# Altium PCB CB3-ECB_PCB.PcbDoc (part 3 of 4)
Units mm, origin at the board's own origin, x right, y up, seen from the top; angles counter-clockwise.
Board outline 195 x 139 mm, 4 copper layers (Top Layer, Layer 1, Layer 2, Bottom Layer), stack 1.56 mm thick; 363 components, 264 nets, 1430 pads, 630 vias.
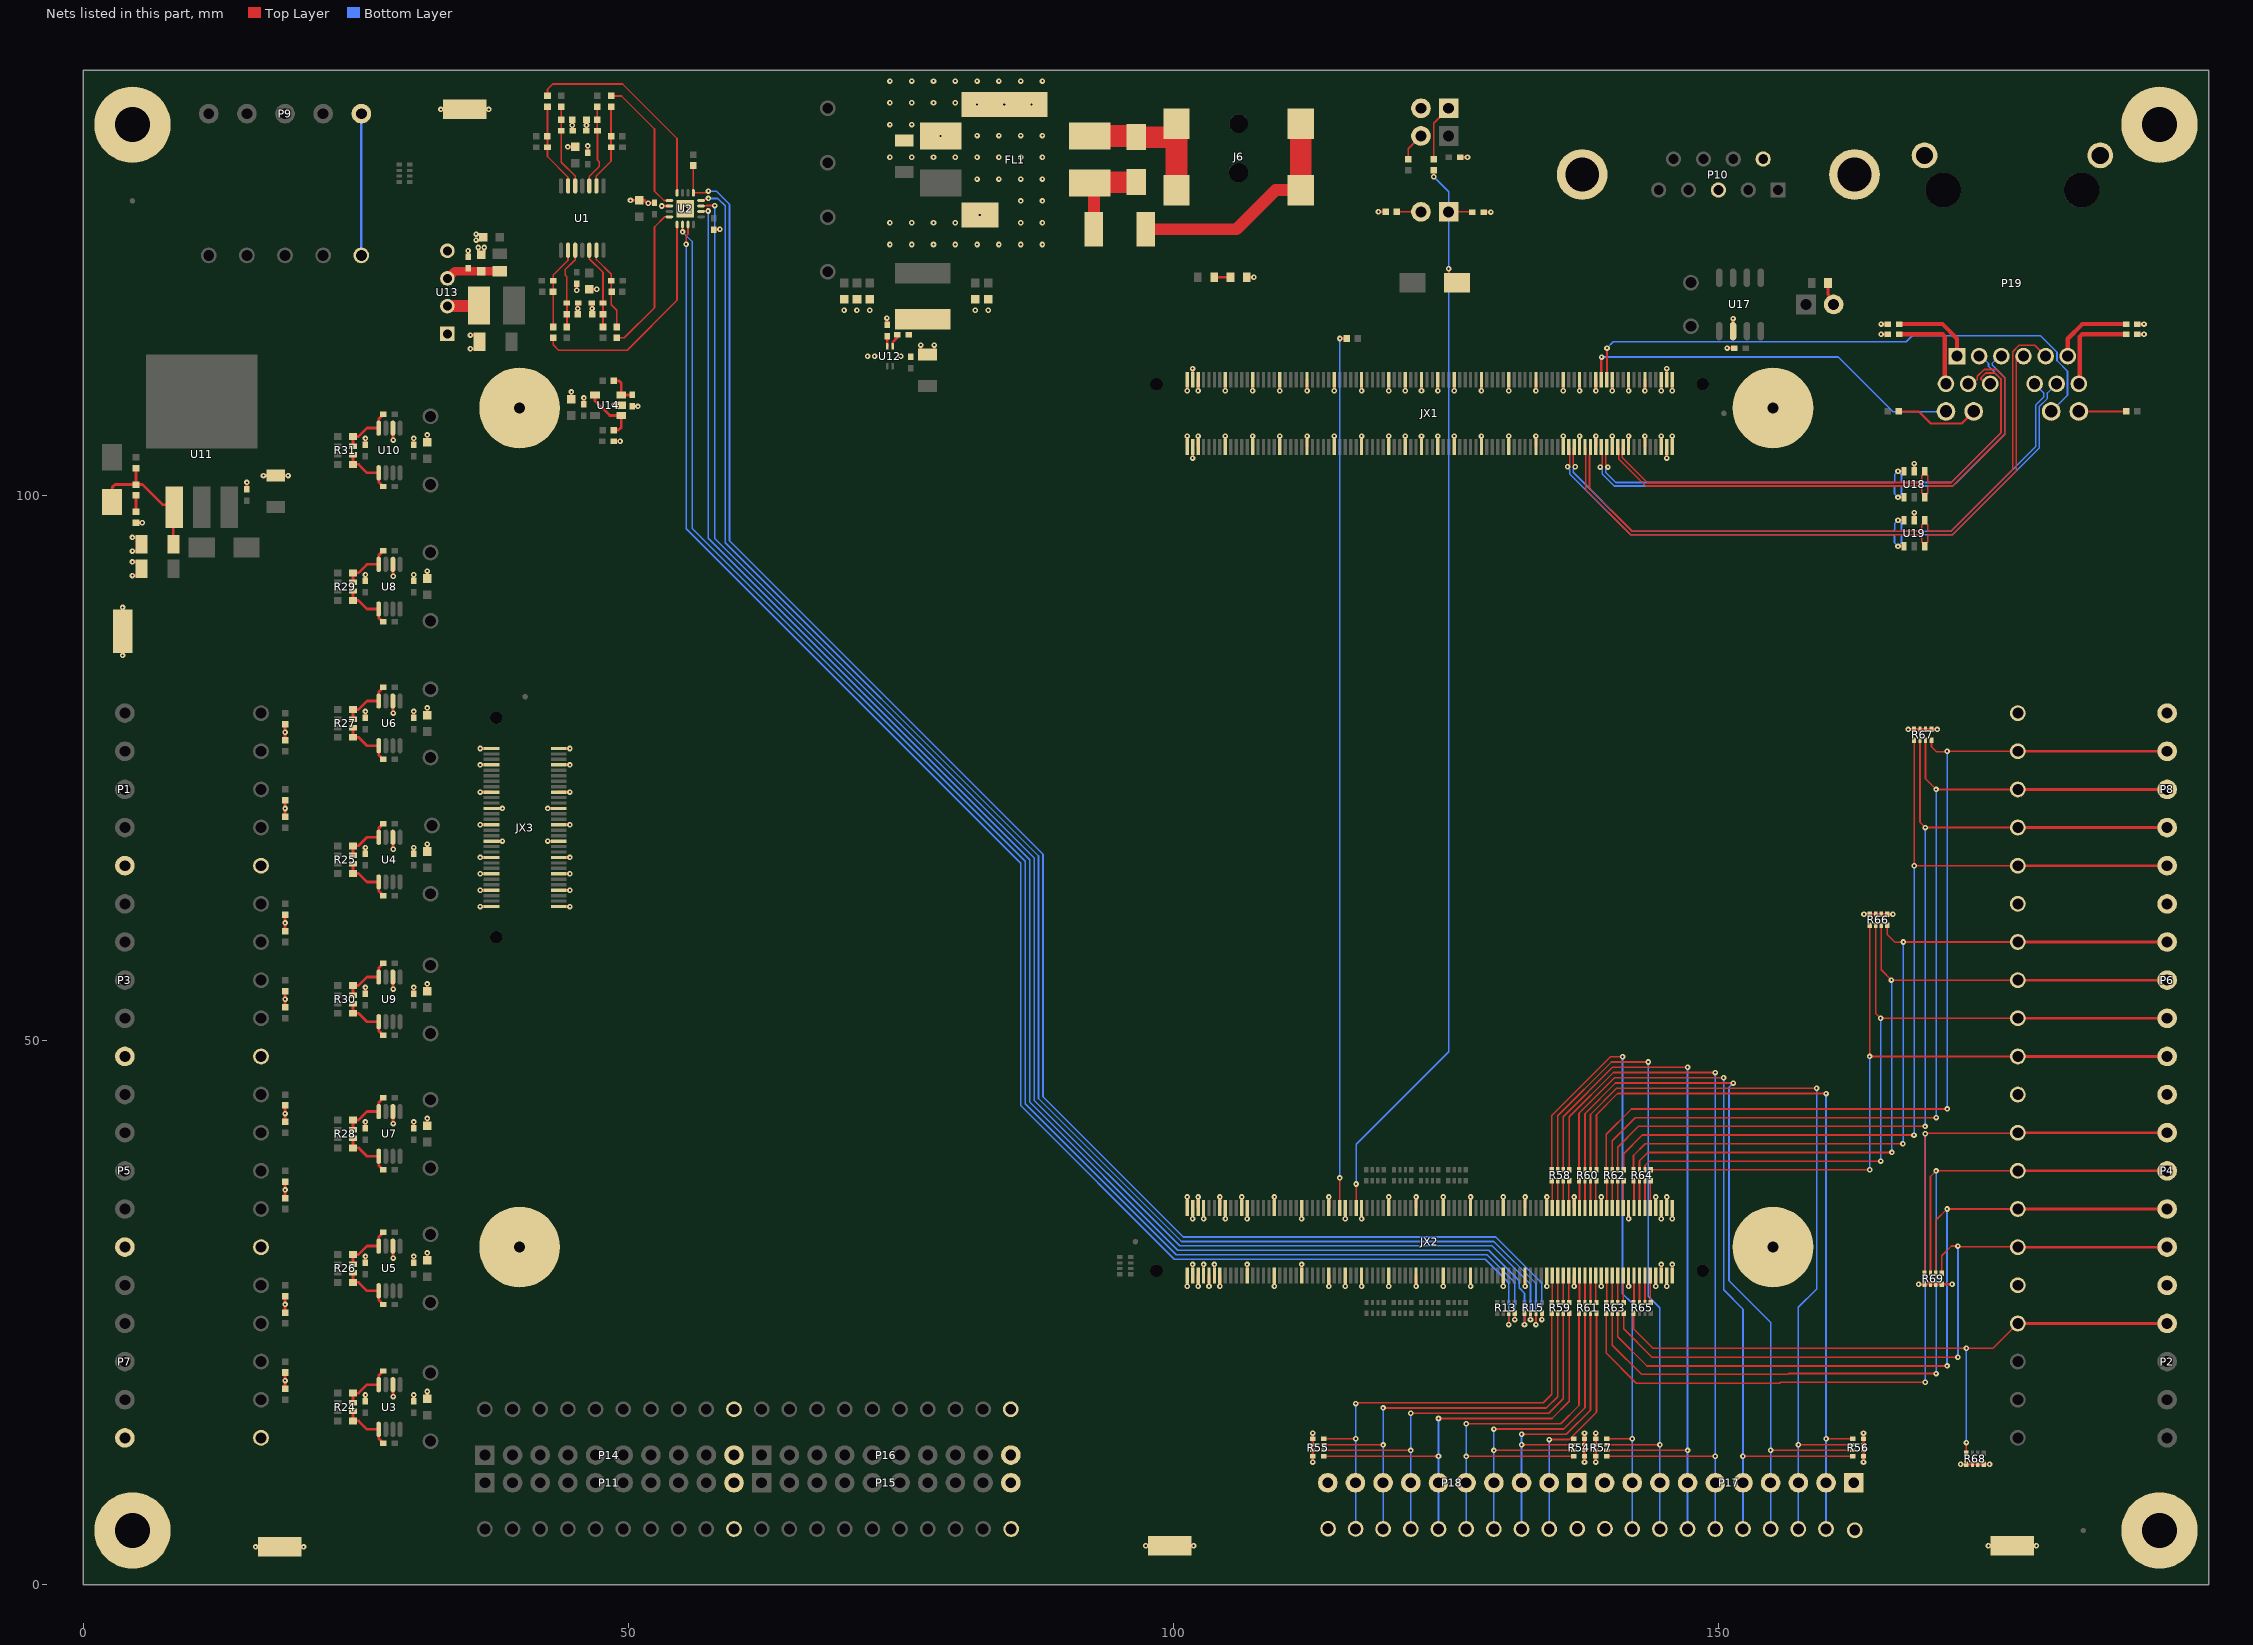
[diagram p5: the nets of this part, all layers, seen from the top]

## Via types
v1: diameter 0.508, hole 0.2, Top Layer to Bottom Layer, tented both sides, 435 vias
v2: diameter 0.508, hole 0.2, Top Layer to Bottom Layer, 194 vias
v3: diameter 0.66, hole 0.33, Top Layer to Bottom Layer, tented both sides, 1 vias

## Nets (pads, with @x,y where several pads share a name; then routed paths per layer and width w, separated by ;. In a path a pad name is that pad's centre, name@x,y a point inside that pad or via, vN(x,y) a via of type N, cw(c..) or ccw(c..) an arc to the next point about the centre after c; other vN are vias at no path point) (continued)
GND: C1.1 C2.1 C3.2 C4.2 C6.1 C7.1 C8.1 C9.1 C11.1 C13.1 C15.1 C18.1 C19.1 C20.1 C21.1 C22.1 C25.1 C28.1 C29.1 C30.1 C31.1 C32.1 C33.1 C38.1 C39.1 C40.1 C41.1 C42.1 C43.1 C46.1 C47.1 C50.1 C51.1 C52.1 C53.1 C56.1 C57.1 C59.1 C60.1 C61.1 C62.1 C63.1 C64.2 C65.2 C66.1 C67.2 C68.1 C69.1 C70.1 C71.1 C72.1 C73.1 C74.1 C75.1 C76.1 C77.1 C78.1 C79.1 C80.1 C81.1 C82.1 C83.1 C84.1 FL1.4 J1.1 J2.1 J3.1 J4.1 J5.1 JX1.1 JX1.2 JX1.3 JX1.6 JX1.9 JX1.12 JX1.15 JX1.18 JX1.21 JX1.26 JX1.31 JX1.36 JX1.41 JX1.44 JX1.47 JX1.50 JX1.53 JX1.58 JX1.63 JX1.68 JX1.73 JX1.78 JX1.83 JX1.88 JX1.89 JX1.90 JX1.91 JX1.92 JX1.93 JX1.98 JX1.103 JX1.108 JX1.113 JX1.118 JX1.123 JX1.128 JX1.131 JX1.134 JX1.137 JX1.140 JX1.145 JX1.150 JX1.155 JX1.160 JX1.163 JX1.166 JX1.169 JX1.172 JX1.175 JX1.178 JX1.179 JX1.180 JX2.1 JX2.2 JX2.3 JX2.4 JX2.7 JX2.8 JX2.11 JX2.12 JX2.17 JX2.22 JX2.27 JX2.30 JX2.33 JX2.38 JX2.43 JX2.48 JX2.53 JX2.59 JX2.63 JX2.67 JX2.72 JX2.77 JX2.82 JX2.87 JX2.88 JX2.89 JX2.90 JX2.91 JX2.92 JX2.93 JX2.94 JX2.99 JX2.104 JX2.109 JX2.114 JX2.118 JX2.122 JX2.128 JX2.133 JX2.138 JX2.143 JX2.148 JX2.151 JX2.154 JX2.159 JX2.164 JX2.169 JX2.174 JX2.175 JX2.176 JX2.177 JX2.178 JX2.179 JX2.180 JX3.1 JX3.4 JX3.9 JX3.12 JX3.15 JX3.18 JX3.21 JX3.24 JX3.27 JX3.30 JX3.31 JX3.34 JX3.37 JX3.40 JX3.43 JX3.46 JX3.49 JX3.52 JX3.57 JX3.60 LED1.K P1.1 P2.1 P3.1 P4.1 P5.1 P6.1 P7.1 P8.1 P9.5 P10.3 P10.6 P10.MH1 P10.MH2 P11.10 P13.2 P14.10 P15.10 P16.10 P17.1 P17.10 P18.1 P18.10 P19.S1 P19.S2 P22.0 P23.0 P24.0 P25.0 P26.1 P27.1 P28.1 P29.1 R3.1 R4.1 R8.1 R14.1 R19.1 R23.1 R34.1 R35.1 R37.1 R38.1 R39.1 R40.1 R54.5 R54.6 R54.7 R54.8 R55.5 R55.6 R55.7 R55.8 R56.5 R56.6 R56.7 R56.8 R57.5 R57.6 R57.7 R57.8 R66.5 R66.6 R66.7 R66.8 R67.5 R67.6 R67.7 R67.8 R68.5 R68.6 R68.7 R68.8 R69.5 R69.6 R69.7 R69.8 R71.1 R72.1 R73.1 R74.1 R75.1 R76.1 R77.1 R78.1 R79.1 R84.1 TP21.1 TP22.1 TP31.1 TP32.1 TP57.1 TP58.1 TP59.1 TP60.1 TP65.1 TP66.1 TP67.1 TP68.1 TP73.1 TP74.1 TP75.1 TP76.1 TP105.1 U2.2 U2.17 U3.6 U4.6 U5.6 U6.6 U7.6 U8.6 U9.6 U10.6 U12.1 U12.9 U13.1 U13.4 U14.2 U17.2 U18.2 U19.2 | length 251.3
  Top Layer w0.25: v2(4.5,92.625) C63.1@4.925,92.625 ; v2(4.5,93.875) C63.1@4.925,93.875 ; v2(4.5,94.875) C62.1@4.925,94.875 ; v2(4.5,96.125) 4.925,96.125 5.35,95.7 C62.1@5.35,95.5 ; R34.1@4.825,97.475 v2(5.4,97.475) ; C61.1@15,100.525 v2(15,101.175) ; v2(16.525,101.8) C60.1@17.65,101.8 v2(18.775,101.8) ; R76.1@18.5,18 v1(18.5,18.75) R77.1@18.5,19.5 ; R72.1@18.5,25 v1(18.5,25.75) R73.1@18.5,26.5 ; R38.1@18.5,35.5 v1(18.5,36.25) R39.1@18.5,37 ; R3.1@18.5,42.5 v1(18.5,43.25) R4.1@18.5,44 ; R78.1@18.5,53 v1(18.5,53.75) R79.1@18.5,54.5 ; R74.1@18.5,60 v1(18.5,60.75) R75.1@18.5,61.5 ; R40.1@18.5,70.5 v1(18.5,71.25) R71.1@18.5,72 ; R35.1@18.5,77.5 v1(18.5,78.25) R37.1@18.5,79 ; C67.2@35.3,121.875 v2(35.3,122.425) ; v2(35.508,113.437) C66.1@35.933,113.437 ; v2(35.508,114.687) C66.1@35.933,114.687 ; v2(36.025,123.4) C65.2@36.475,123.4 ; v2(36.025,123.95) C65.2@36.475,123.95 ; C64.2@36.225,122.275 v2(36.225,122.725) ; C64.2@36.275,122.275 C64.2@36.5,122.05 ; C64.2@36.775,122.275 v2(36.775,122.725) ; C79.1@44.775,108.8 v2(44.775,109.475) ; v1(45.272,118.8) C2.1@45.272,119.417 ; C77.1@45.925,108.35 v2(45.925,108.925) ; C4.2@46.27,131.435 v1(46.271,132.052) ; v2(48.65,108.25) U14.2@49.35,108.25 ; C81.1@48.675,104.95 v2(49.25,104.95) ; v1(50.2,127.05) C9.1@51,127.05 51.497,127.05 51.759,126.789 v1(51.828,126.789) ; C80.1@50.375,108.15 v2(50.875,108.15) ; v1@51.898,126.789 v1(51.828,126.789) ; C8.1@52.4,126.825 52.382,126.807 51.847,126.807 v1(51.828,126.789) ; v1(53.072,126.534) U2.2@53.772,126.534 ; C7.1@57.828,124.346 57.855,124.373 58.373,124.373 v1(58.4,124.4) ; v2(73.725,116.25) 73.738,116.237 73.738,115.663 C72.1@73.75,115.65 ; C68.1@76.825,113.35 v2(76.825,113.775) ; C68.1@78.075,113.35 v2(78.075,113.775) ; LED1.K@106.75,120 v2(107.4,120) ; v2(118.825,126) R84.1@119.5,126 ; C78.1@126.325,131 v2(127,131) ; C84.1@128.475,125.975 v2(129.15,125.975) ; v2(150.825,113.5) C70.1@151.475,113.5 ; U17.2@151.365,115.05 151.365,116.165 v2@151.4,116.2 ; v2(164.95,114.763) C76.1@165.55,114.763 ; v2(164.95,115.7) C75.1@165.55,115.7 ; U19.2@168,97.7 v1(168,98.4) ; U18.2@168,102.2 v1(168,102.9) ; C73.1@188.475,114.763 v2(189.075,114.763) ; C74.1@188.475,115.7 v2(189.075,115.7)
  Top Layer w0.254: C20.1@25.875,16.856 v1(25.875,17.432) ; C30.1@25.875,29.569 v1(25.875,30.145) ; C40.1@25.875,41.914 v1(25.875,42.489) ; C50.1@25.875,54.258 v1(25.875,54.834) ; C25.1@25.875,67.085 v1(25.875,67.661) ; C33.1@25.875,79.582 v1(25.875,80.158) ; C43.1@25.875,92.129 v1(25.875,92.705) ; C53.1@25.875,104.626 v1(25.875,105.202) ; U10.6@28.397,106.151 28.41,106.138 28.41,105.07 v1(28.429,105.051) ; v1@28.41,17.3 U3.6@28.41,18.368 ; v1@28.41,30.013 U5.6@28.41,31.081 ; v1@28.41,42.358 U7.6@28.41,43.426 ; v1@28.41,54.702 U9.6@28.41,55.77 ; v1@28.41,67.529 U4.6@28.41,68.597 ; v1@28.41,80.026 U6.6@28.41,81.094 ; v1@28.41,92.573 U8.6@28.41,93.641 ; C18.1@30.305,16.856 v1(30.305,17.433) ; C21.1@30.305,29.569 v1(30.305,30.145) ; C28.1@30.305,41.914 v1(30.305,42.49) ; C31.1@30.305,54.258 v1(30.305,54.834) ; C38.1@30.305,67.085 v1(30.305,67.661) ; C41.1@30.305,79.582 v1(30.305,80.158) ; C46.1@30.305,92.129 v1(30.305,92.705) ; C51.1@30.305,104.626 v1(30.305,105.202) ; C52.1@31.548,104.851 31.55,104.853 v1(31.55,105.525) ; C19.1@31.548,17.081 v1(31.55,17.755) ; C22.1@31.55,29.796 v1(31.55,30.468) ; C29.1@31.55,42.141 v1(31.55,42.812) ; C32.1@31.55,54.485 v1(31.55,55.157) ; C39.1@31.55,67.312 v1(31.55,67.984) ; C42.1@31.55,79.809 v1(31.55,80.481) ; C47.1@31.55,92.356 v1(31.55,93.028) ; v1(36.421,62.255) JX3.31@37.435,62.255 ; v1(36.421,63.755) JX3.34@37.435,63.755 ; v1(36.421,65.255) JX3.37@37.435,65.255 ; v1(36.421,66.755) JX3.40@37.435,66.755 ; v1(36.421,69.755) JX3.46@37.435,69.755 ; v1(36.421,72.755) JX3.52@37.435,72.755 ; v1(36.421,75.255) JX3.57@37.435,75.255 ; v1(36.421,76.755) JX3.60@37.435,76.755 ; JX3.43@37.435,68.255 v1(38.45,68.255) ; JX3.49@37.435,71.255 v1(38.45,71.255) ; v1(42.611,68.255) JX3.18@43.625,68.255 ; v1(42.611,71.255) JX3.12@43.625,71.255 ; JX3.30@43.625,62.255 v1(44.64,62.255) ; JX3.27@43.625,63.755 v1(44.64,63.755) ; JX3.24@43.625,65.255 v1(44.64,65.255) ; JX3.21@43.625,66.755 v1(44.64,66.755) ; JX3.15@43.625,69.755 v1(44.64,69.755) ; JX3.9@43.625,72.755 v1(44.64,72.755) ; JX3.4@43.625,75.255 v1(44.64,75.255) ; JX3.1@43.625,76.755 v1(44.64,76.755) ; v1(44.443,131.952) C3.2@45.015,131.952 ; C15.1@44.852,133.432 v1(44.852,133.94) R23.1@44.852,134.448 ; R8.1@45.366,116.617 v1(45.366,117.125) C6.1@45.366,117.633 ; C13.1@46.162,133.432 v1(46.162,133.94) R19.1@46.162,134.448 ; C1.1@46.517,118.889 46.528,118.9 v1(47.1,118.9) ; R14.1@46.676,116.617 v1(46.676,117.125) C11.1@46.676,117.633 ; v1(101.28,27.409) JX2.180@101.28,28.41 ; JX2.1@101.28,34.6 v1(101.28,35.601) ; JX1.90@101.28,104.41 v1(101.28,105.422) ; v1(101.28,109.588) JX1.91@101.28,110.6 ; JX2.179@101.78,28.41 v1(101.78,29.411) ; v1(101.78,33.599) JX2.2@101.78,34.6 ; v1(101.78,103.398) JX1.89@101.78,104.41 ; JX1.92@101.78,110.6 v1(101.78,111.612) ; v1(102.28,27.409) JX2.178@102.28,28.41 ; JX2.3@102.28,34.6 v1(102.28,35.601) ; JX1.88@102.28,104.41 v1(102.28,105.422) ; v1(102.28,109.588) JX1.93@102.28,110.6 ; JX2.177@102.78,28.41 v1(102.78,29.411) ; v1(102.78,33.599) JX2.4@102.78,34.6 ; v1@103.28,27.409 JX2.176@103.28,28.41 ; JX2.175@103.78,28.41 v1(103.78,29.411) ; v1(104.28,27.409) JX2.174@104.28,28.41 ; JX2.7@104.28,34.6 v1(104.28,35.601) ; v1(104.78,33.599) JX2.8@104.78,34.6 ; JX1.83@104.78,104.41 v1(104.78,105.422) ; v1(104.78,109.588) JX1.98@104.78,110.6 ; JX2.11@106.28,34.6 v1(106.28,35.601) ; JX2.169@106.78,28.41 v1(106.78,29.411) ; v1(106.78,33.599) JX2.12@106.78,34.6 ; JX1.78@107.28,104.41 v1@107.28,105.422 ; v1@107.28,109.588 JX1.103@107.28,110.6 ; v1(109.28,27.409) JX2.164@109.28,28.41 ; JX2.17@109.28,34.6 v1(109.28,35.601) ; JX1.73@109.78,104.41 v1(109.78,105.422) ; v1(109.78,109.588) JX1.108@109.78,110.6 ; JX2.159@111.78,28.41 v1(111.78,29.411) ; v1(111.78,33.599) JX2.22@111.78,34.6 ; JX1.68@112.28,104.41 v1(112.28,105.422) ; v1(112.28,109.588) JX1.113@112.28,110.6 ; v1(112.796,11.28) R55.8@112.796,11.81 R55.7@112.796,12.36 R55.6@112.796,12.86 R55.5@112.796,13.41 v1(112.796,13.941) ; v1(114.28,27.409) JX2.154@114.28,28.41 ; JX2.27@114.28,34.6 v1(114.28,35.601) ; JX1.63@114.78,104.41 v1(114.78,105.422) ; v1(114.78,109.588) JX1.118@114.78,110.6 ; v1(115.78,27.409) JX2.151@115.78,28.41 ; v1(115.78,33.599) JX2.30@115.78,34.6 ; v1(117.28,27.409) JX2.148@117.28,28.41 ; v1(117.28,33.599) JX2.33@117.28,34.6 ; JX1.58@117.28,104.41 v1(117.28,105.422) ; v1(117.28,109.588) JX1.123@117.28,110.6 ; v1(119.78,27.409) JX2.143@119.78,28.41 ; JX2.38@119.78,34.6 v1(119.78,35.601) ; JX1.53@119.78,104.41 v1(119.78,105.422) ; v1(119.78,109.588) JX1.128@119.78,110.6 ; JX1.50@121.28,104.41 v1(121.28,105.422) ; v1(121.28,109.588) JX1.131@121.28,110.6 ; v1(122.28,27.409) JX2.138@122.28,28.41 ; JX2.43@122.28,34.6 v1(122.28,35.601) ; JX1.47@122.78,104.41 v1(122.78,105.422) ; v1(122.78,109.588) JX1.134@122.78,110.6 ; JX1.44@124.28,104.41 v1@124.28,105.422 ; v1@124.28,109.588 JX1.137@124.28,110.6 ; v1(124.78,27.409) JX2.133@124.78,28.41 ; JX2.48@124.78,34.6 v1(124.78,35.601) ; JX1.41@125.78,104.41 v1(125.78,105.422) ; v1(125.78,109.588) JX1.140@125.78,110.6 ; v1(127.28,27.409) JX2.128@127.28,28.41 ; JX2.53@127.28,34.6 v1(127.28,35.601) ; JX1.36@128.28,104.41 v1(128.28,105.422) ; v1(128.28,109.588) JX1.145@128.28,110.6 ; v1(130.28,27.409) JX2.122@130.28,28.41 ; JX2.59@130.28,34.6 v1(130.28,35.601) ; JX1.31@130.78,104.41 v1@130.78,105.422 ; v1@130.78,109.588 JX1.150@130.78,110.6 ; v1(132.28,27.409) JX2.118@132.28,28.41 ; JX2.63@132.28,34.6 v1(132.28,35.601) ; JX1.26@133.28,104.41 v1(133.28,105.422) ; v1(133.28,109.588) JX1.155@133.28,110.6 ; v1(134.28,27.409) JX2.114@134.28,28.41 ; JX2.67@134.28,34.6 v1(134.28,35.601) ; JX1.21@135.78,104.41 v1(135.78,105.422) ; v1(135.78,109.588) JX1.160@135.78,110.6 ; v1(136.78,27.409) JX2.109@136.78,28.41 ; JX2.72@136.78,34.6 v1(136.78,35.601) ; JX1.18@137.28,104.41 v1(137.28,105.422) ; v1(137.28,109.588) JX1.163@137.28,110.6 ; v1(137.736,11.28) R54.5@137.736,11.81 R54.6@137.736,12.36 R54.7@137.736,12.86 R54.8@137.736,13.41 v1(137.736,13.941) ; v1(138.768,11.28) R57.8@138.768,11.81 R57.7@138.768,12.36 R57.6@138.768,12.86 R57.5@138.768,13.41 v1(138.768,13.941) ; JX1.15@138.78,104.41 v1(138.78,105.422) ; v1(138.78,109.588) JX1.166@138.78,110.6 ; v1(139.28,27.409) JX2.104@139.28,28.41 ; JX2.77@139.28,34.6 v1(139.28,35.601) ; JX1.12@140.28,104.41 v1(140.28,105.422) ; v1(140.28,109.588) JX1.169@140.28,110.6 ; v1(141.78,27.409) JX2.99@141.78,28.41 ; v1(141.78,33.599) JX2.82@141.78,34.6 ; JX1.9@141.78,104.41 v1(141.78,105.422) ; v1(141.78,109.588) JX1.172@141.78,110.6 ; JX1.6@143.28,104.41 v1(143.28,105.422) ; v1(143.28,109.588) JX1.175@143.28,110.6 ; v1(144.28,27.409) JX2.94@144.28,28.41 ; JX2.87@144.28,34.6 v1(144.28,35.601) ; JX2.93@144.78,28.41 v1(144.78,29.411) ; v1(144.78,33.599) JX2.88@144.78,34.6 ; JX1.3@144.78,104.41 v1(144.78,105.422) ; v1(144.78,109.588) JX1.178@144.78,110.6 ; v1(145.28,27.409) JX2.92@145.28,28.41 ; JX2.89@145.28,34.6 v1(145.28,35.601) ; v1(145.28,103.398) JX1.2@145.28,104.41 ; JX1.179@145.28,110.6 v1(145.28,111.612) ; JX2.91@145.78,28.41 v1(145.78,29.411) ; v1(145.78,33.599) JX2.90@145.78,34.6 ; JX1.1@145.78,104.41 v1(145.78,105.422) ; v1(145.78,109.588) JX1.180@145.78,110.6 ; v1(163.336,11.28) R56.5@163.336,11.81 R56.6@163.336,12.36 R56.7@163.336,12.86 R56.8@163.336,13.41 v1(163.336,13.941) ; v1(163.38,61.549) R66.8@163.911,61.549 R66.7@164.461,61.549 R66.6@164.961,61.549 R66.5@165.511,61.549 v1(166.041,61.549) ; v1(167.444,78.504) R67.8@167.975,78.504 R67.7@168.525,78.504 R67.6@169.025,78.504 R67.5@169.575,78.504 v1(170.105,78.504) ; v1(168.397,27.601) R69.5@168.927,27.601 R69.6@169.477,27.601 R69.7@169.977,27.601 R69.8@170.527,27.601 v1(171.464,27.601) ; v1(172.248,11.073) R68.5@172.778,11.073 R68.6@173.328,11.073 R68.7@173.828,11.073 R68.8@174.378,11.073 v1(174.909,11.073)
  Top Layer w0.305: v1(3.6,85.3) J2.1@3.6,87.5 v1(3.6,89.7) ; v1(15.8,3.5) J4.1@18,3.5 v1(20.2,3.5) ; v1(32.8,135.4) J5.1@35,135.4 v1(37.2,135.4) ; v1(97.47,3.6) v1(101.87,3.6) ; v1(174.8,3.6) J1.1@177,3.6 v1(179.2,3.6)
  Bottom Layer w0.25: TP105.1@25.5,122 P9.5@25.5,135
  other v1: 28.429,17.281 103.28,27.409 28.429,29.994 28.429,42.339 28.429,54.683 28.429,67.51 28.429,80.007 28.429,92.554 107.28,105.422 124.28,105.422 130.78,105.422 107.28,109.588 124.28,109.588 130.78,109.588
  other v2: 71.95,112.75 72.6,112.75 75,112.75 151.365,116.2 69.8,116.975 70.975,116.975 72.15,116.975 81.825,116.975 83.025,116.975 74,123 76,123 78,123 80,123 82,123 84,123 86,123 88,123 74,125 76,125 78,125 80,125 86,125 88,125 82.25,125.7 86,127 88,127 82,129 84,129 86,129 88,129 74,131 76,131 78,131 80,131 82,131 84,131 86,131 88,131 78.65,132.95 82,133 84,133 86,133 88,133 74,134 76,134 82,135.85 84.5,135.85 87,135.85 74,136 76,136 78,136 80,136 74,138 76,138 78,138 80,138 82,138 84,138 86,138 88,138
  other v3: 55.222,126.284
GPI0: JX2.105 R61.5 | length 2.5
  Top Layer w0.152: R61.5@138.78,25.92 JX2.105@138.78,28.41
GPI1: JX2.106 R61.6 | length 2.5
  Top Layer w0.152: R61.6@138.28,25.92 JX2.106@138.28,28.41
GPI2: JX2.107 R61.7 | length 2.5
  Top Layer w0.152: R61.7@137.78,25.92 JX2.107@137.78,28.41
GPI3: JX2.108 R61.8 | length 2.5
  Top Layer w0.152: R61.8@137.28,25.92 JX2.108@137.28,28.41
GPI4: JX2.110 R59.5 | length 2.5
  Top Layer w0.152: R59.5@136.28,25.92 JX2.110@136.28,28.41
GPI5: JX2.111 R59.6 | length 2.5
  Top Layer w0.152: R59.6@135.78,25.92 JX2.111@135.78,28.41
GPI6: JX2.112 R59.7 | length 2.5
  Top Layer w0.152: R59.7@135.28,25.92 JX2.112@135.28,28.41
GPI7: JX2.113 R59.8 | length 2.5
  Top Layer w0.152: R59.8@134.78,25.92 JX2.113@134.78,28.41
GPI-0: P18.2 R54.1 R61.4 TP41.1 | length 22.7
  Top Layer w0.152: v1(134.497,13.343) 136.326,13.343 138.83,15.848 R61.4@138.83,24.92
  Bottom Layer w0.152: TP41.1@134.497,5.136 P18.2@134.497,9.381 v1(134.497,13.343) v1@134.497,13.42
GPI-1: P18.3 R54.2 R61.3 TP42.1 | length 29.6
  Top Layer w0.152: v1@131.932,13.83 v1(131.957,13.83) 136.067,13.83 138.28,16.043 R61.3@138.28,24.92 ; v1(131.957,12.861) R54.2@136.736,12.86
  Bottom Layer w0.152: TP42.1@131.957,5.136 P18.3@131.957,9.381 v1(131.957,12.861) v1(131.957,13.83)
GPI-2: P18.4 R54.3 R61.2 TP47.1 | length 34.3
  Top Layer w0.152: v1(129.417,12.353) 129.425,12.36 R54.3@136.736,12.36 ; v1(129.417,14.312) 135.843,14.312 137.78,16.25 R61.2@137.78,24.92
  Bottom Layer w0.152: TP47.1@129.417,5.136 P18.4@129.417,9.381 v1(129.417,12.353) v1@129.417,14.236
GPI-3: P18.5 R54.4 R61.1 TP48.1 | length 39
  Top Layer w0.152: v1(126.877,11.794) 126.894,11.81 R54.4@136.736,11.81 ; v1@126.903,14.795 135.547,14.795 137.23,16.478 R61.1@137.23,24.92
  Bottom Layer w0.152: TP48.1@126.877,5.136 P18.5@126.877,9.381 v1(126.877,11.794) v1(126.877,14.795)
GPI-4: P18.6 R55.1 R59.4 TP53.1 | length 41.4
  Top Layer w0.152: R55.1@113.796,11.81 124.328,11.81 v1(124.337,11.819) ; v1(124.337,15.277) 134.757,15.277 136.33,16.851 R59.4@136.33,24.92
  Bottom Layer w0.152: TP53.1@124.337,5.136 P18.6@124.337,9.381 v1(124.337,11.819) v1(124.337,15.277)
GPI-5: P18.7 R55.2 R59.3 TP54.1 | length 41
  Top Layer w0.152: R55.2@113.796,12.36 121.79,12.36 v1(121.797,12.353) ; v1(121.797,15.76) 134.462,15.76 135.78,17.078 R59.3@135.78,24.92
  Bottom Layer w0.152: TP54.1@121.797,5.136 P18.7@121.797,9.381 v1(121.797,12.353) v1(121.797,15.76)
GPI-6: P18.8 R55.3 R59.2 TP55.1 | length 40.7
  Top Layer w0.152: R55.3@113.796,12.86 v1(119.257,12.86) ; v1(119.257,16.243) 134.237,16.243 135.28,17.286 R59.2@135.28,24.92
  Bottom Layer w0.152: TP55.1@119.257,5.136 P18.8@119.257,9.381 119.257,12.875 v1(119.257,16.243)
GPI-7: P18.9 R55.4 R59.1 TP56.1 | length 40.2
  Top Layer w0.152: R55.4@113.796,13.41 116.734,13.41 v1(116.743,13.42) ; v1@116.717,16.725 132.74,16.725 133.942,16.725 134.73,17.513 R59.1@134.73,24.92
  Bottom Layer w0.152: TP56.1@116.717,5.136 116.749,5.167 116.749,9.381 116.749,13.42 v1(116.749,16.649)
GPO0: JX2.76 R60.4 | length 2.5
  Top Layer w0.152: JX2.76@138.78,34.6 R60.4@138.78,37.096
GPO1: JX2.75 R60.3 | length 2.5
  Top Layer w0.152: JX2.75@138.28,34.6 R60.3@138.28,37.096
GPO2: JX2.74 R60.2 | length 2.5
  Top Layer w0.152: JX2.74@137.78,34.6 R60.2@137.78,37.096
GPO3: JX2.73 R60.1 | length 2.5
  Top Layer w0.152: JX2.73@137.28,34.6 R60.1@137.28,37.096
GPO4: JX2.71 R58.4 | length 2.5
  Top Layer w0.152: JX2.71@136.28,34.6 R58.4@136.28,37.096
GPO5: JX2.70 R58.3 | length 2.5
  Top Layer w0.152: JX2.70@135.78,34.6 R58.3@135.78,37.096
GPO6: JX2.69 R58.2 | length 2.5
  Top Layer w0.152: JX2.69@135.28,34.6 R58.2@135.28,37.096
GPO7: JX2.68 R58.1 | length 2.5
  Top Layer w0.152: JX2.68@134.78,34.6 R58.1@134.78,37.096
GPO-0: P17.2 R56.1 R60.5 TP1.1 | length 69.3
  Top Layer w0.152: R60.5@138.83,38.096 138.83,43.153 140.771,45.093 v1(159.897,45.093) ; v1(159.897,13.42) 159.907,13.41 R56.1@162.336,13.41
  Bottom Layer w0.152: TP1.1@159.893,5.139 159.893,9.381 159.893,13.42 159.893,42.176 159.893,45.089 v1(159.897,45.093)
GPO-1: P17.3 R56.2 R60.6 TP2.1 | length 72.9
  Top Layer w0.152: R60.6@138.28,38.096 138.28,43.177 140.679,45.576 v1(159.034,45.576) ; v1(157.357,12.861) R56.2@162.336,12.86
  Bottom Layer w0.152: TP2.1@157.353,5.139 157.353,9.381 157.353,12.861 157.353,25.481 159.034,27.161 v1(159.034,45.576)
GPO-2: P17.4 R56.3 R60.7 TP3.1 | length 70.1
  Top Layer w0.152: R60.7@137.78,38.096 137.78,43.252 140.587,46.059 v1(151.388,46.059) ; v1(154.813,12.36) R56.3@162.336,12.36
  Bottom Layer w0.152: v1(151.388,46.059) 151,45.67 151,27.905 154.813,24.092 v1(154.813,12.36) 154.813,9.381 TP3.1@154.813,5.139
GPO-3: P17.5 R56.4 R60.8 TP4.1 | length 72
  Top Layer w0.152: R60.8@137.23,38.096 137.23,43.277 140.495,46.541 v1(150.499,46.541) ; v1(152.277,11.819) 152.286,11.81 R56.4@162.336,11.81
  Bottom Layer w0.152: v1(150.499,46.541) 150.499,27.085 152.273,25.311 152.273,11.819 152.273,9.381 TP4.1@152.273,5.139
GPO-4: P17.6 R57.1 R58.5 TP9.1 | length 71.8
  Top Layer w0.152: R58.5@136.33,38.096 136.33,42.952 140.403,47.024 v1(149.737,47.024) ; R57.1@139.768,11.81 149.728,11.81 v1(149.737,11.819)
  Bottom Layer w0.152: TP9.1@149.733,5.139 149.733,11.819 149.733,43.802 149.733,47.02 v1(149.737,47.024)
GPO-5: P17.7 R57.2 R58.6 TP10.1 | length 68
  Top Layer w0.152: R58.6@135.78,38.096 135.78,42.976 140.311,47.506 v1(147.197,47.506) ; R57.2@139.768,12.36 147.19,12.36 v1(147.197,12.353)
  Bottom Layer w0.152: TP10.1@147.193,5.139 147.193,12.353 147.193,44.208 147.193,47.502 v1(147.197,47.506)
GPO-6: P17.8 R57.3 R58.7 TP15.1 | length 63.3
  Top Layer w0.152: R58.7@135.28,38.096 135.28,43.051 140.218,47.989 v1(143.591,47.989) ; R57.3@139.768,12.86 v1(144.657,12.861)
  Bottom Layer w0.152: v1@143.591,47.811 143.591,26.501 144.653,25.438 TP15.1@144.653,5.139
GPO-7: P17.9 R57.4 R58.8 TP16.1 | length 59.8
  Top Layer w0.152: R58.8@134.73,38.096 134.73,43.076 140.126,48.472 v1(141.228,48.472) ; R57.4@139.768,13.41 142.108,13.41 v1(142.117,13.42)
  Bottom Layer w0.152: v1(141.228,48.472) 141.228,26.729 142.113,25.844 142.113,13.42 142.113,9.381 TP16.1@142.113,5.139
MB_nFLT: C84.2 D4.A JX2.32 P21.1 R44.1 | length 102.8
  Top Layer w0.152: JX2.32@116.78,34.6 v1(116.78,36.795) ; v1@123.909,129.313 R44.1@123.909,129.821 ; 125.27,120.4 v2(125.27,120.775) ; P21.1@125.27,126 127.4,126 C84.2@127.425,125.975 ; D4.A@125.3,120.225 D4.A@126.05,119.475
  Bottom Layer w0.152: v1(116.78,36.795) 116.78,40.44 125.27,48.93 v2(125.27,120.775) P21.1@125.27,126 125.27,127.854 v1(123.909,129.215)
MB_RDY: JX2.29 R41.2 | length 80.4
  Top Layer w0.152: JX2.29@115.28,34.6 v1(115.28,37.35)
  Top Layer w0.254: v1@115.334,114.375 R41.2@115.95,114.375
  Bottom Layer w0.152: v1@115.291,37.361 v1(115.291,114.375)
NetC5_1: C5.1 R5.1 R6.1 U1.2 | length 8.5
  Top Layer w0.152: R6.1@43.112,115.432 43.112,116.617 43.112,117.633 ; 43.112,116.744 43.121,120.201 44.471,121.551 U1.2@44.471,122.476
NetC6_2: C6.2 R7.1 R8.2 U1.3 | length 7.5
  Top Layer w0.152: C6.2@44.34,117.633 44.34,120.06 44.217,120.183 44.217,120.7 45.121,121.604 U1.3@45.121,122.476 ; R7.1@44.366,115.432 R8.2@44.366,116.617 C6.2@44.366,117.633
NetC10_1: C10.1 R9.1 R10.1 U1.6 | length 7.8
  Top Layer w0.152: U1.6@47.071,122.476 47.071,121.625 48.438,120.258 C10.1@48.438,119.665 48.438,117.464 48.946,116.956 R10.1@48.946,115.432
NetC11_2: C11.2 R12.1 R14.2 U1.5 | length 7.9
  Top Layer w0.152: U1.5@46.421,122.476 46.421,121.7 47.676,120.446 C11.2@47.676,117.633 ; C11.2@47.452,117.807 47.626,117.633 C11.2@47.676,117.633 ; R12.1@47.676,115.432 R14.2@47.676,116.617 C11.2@47.676,117.633
NetC12_1: C12.1 R16.1 R17.1 U1.9 | length 8.8
  Top Layer w0.152: U1.9@47.071,128.376 47.071,129.301 48.416,130.645 48.416,133.873 48.416,134.254 ; 48.416,133.238 48.416,133.432 48.416,134.448 R17.1@48.416,135.633
NetC13_2: C13.2 R18.1 R19.2 U1.10 | length 7.7
  Top Layer w0.152: U1.10@46.421,128.376 46.421,129.246 47.325,130.15 47.325,130.585 47.172,130.739 C13.2@47.172,133.432 ; C13.2@47.162,133.432 47.162,133.873 47.162,134 R19.2@47.162,134.448 R18.1@47.162,135.633
NetC14_1: C14.1 R20.1 R21.1 U1.13 | length 8
  Top Layer w0.152: R21.1@42.582,135.633 C14.1@42.582,131.908 42.582,131.068 44.471,129.178 U1.13@44.471,128.376
NetC15_2: C15.2 R22.1 R23.2 U1.12 | length 7.8
  Top Layer w0.152: R22.1@43.852,135.633 R23.2@43.852,134.448 C15.2@43.852,133.432 43.852,130.548 45.121,129.279 U1.12@45.121,128.376
NetC16_1: C16.1 R24.7 R24.8 U3.8 | length 5
  Top Layer w0.254: R24.7@24.741,16.731 R24.8@24.741,17.601 25.244,17.602 26.024,18.381 U3.8@27.097,18.381 27.097,19.212 C16.1@27.524,19.638
NetC17_1: C17.1 R25.7 R25.8 U4.8 | length 5
  Top Layer w0.254: R25.7@24.741,66.96 R25.8@24.741,67.83 25.244,67.83 26.024,68.61 U4.8@27.097,68.61 27.097,69.44 C17.1@27.524,69.867
NetC23_1: C23.1 R24.5 R24.6 U3.1 | length 5
  Top Layer w0.254: R24.6@24.741,15.931 R24.5@24.741,15.061 25.244,15.061 26.024,14.282 U3.1@27.097,14.282 27.097,13.451 C23.1@27.524,13.024
NetC24_1: C24.1 R25.5 R25.6 U4.1 | length 5
  Top Layer w0.254: R25.6@24.741,66.16 R25.5@24.741,65.29 25.244,65.29 26.024,64.51 U4.1@27.097,64.51 27.097,63.68 C24.1@27.524,63.253
NetC26_1: C26.1 R26.7 R26.8 U5.8 | length 5
  Top Layer w0.254: R26.7@24.741,29.444 R26.8@24.741,30.314 25.244,30.314 26.024,31.094 U5.8@27.097,31.094 27.097,31.924 C26.1@27.524,32.351
NetC27_1: C27.1 R27.7 R27.8 U6.8 | length 5
  Top Layer w0.254: R27.7@24.741,79.457 R27.8@24.741,80.327 25.244,80.327 26.024,81.107 U6.8@27.097,81.107 27.097,81.937 C27.1@27.524,82.364
NetC34_1: C34.1 R26.5 R26.6 U5.1 | length 5
  Top Layer w0.254: R26.6@24.741,28.644 R26.5@24.741,27.774 25.244,27.774 26.024,26.994 U5.1@27.097,26.994 27.097,26.164 C34.1@27.524,25.737
NetC35_1: C35.1 R27.5 R27.6 U6.1 | length 5
  Top Layer w0.254: R27.6@24.741,78.657 R27.5@24.741,77.787 25.244,77.787 26.024,77.007 U6.1@27.097,77.007 27.097,76.177 C35.1@27.524,75.75
NetC36_1: C36.1 R28.7 R28.8 U7.8 | length 5
  Top Layer w0.254: R28.7@24.741,41.789 R28.8@24.741,42.659 25.244,42.659 26.024,43.439 U7.8@27.097,43.439 27.097,44.269 C36.1@27.524,44.695
NetC37_1: C37.1 R29.7 R29.8 U8.8 | length 5
  Top Layer w0.254: R29.7@24.741,92.004 R29.8@24.741,92.874 25.244,92.874 26.024,93.654 U8.8@27.097,93.654 27.097,94.485 C37.1@27.524,94.911
NetC44_1: C44.1 R28.5 R28.6 U7.1 | length 5
  Top Layer w0.254: R28.6@24.741,40.989 R28.5@24.741,40.119 25.244,40.119 26.024,39.339 U7.1@27.097,39.339 27.097,38.508 C44.1@27.524,38.081
NetC45_1: C45.1 R29.5 R29.6 U8.1 | length 5
  Top Layer w0.254: R29.6@24.741,91.204 R29.5@24.741,90.334 25.244,90.334 26.024,89.554 U8.1@27.097,89.554 27.097,88.724 C45.1@27.524,88.297
NetC48_1: C48.1 R30.7 R30.8 U9.8 | length 5
  Top Layer w0.254: R30.7@24.741,54.133 R30.8@24.741,55.003 25.244,55.003 26.024,55.783 U9.8@27.097,55.783 27.097,56.613 C48.1@27.524,57.04
NetC49_1: C49.1 R31.7 R31.8 U10.8 | length 5
  Top Layer w0.254: R31.7@24.741,104.501 R31.8@24.741,105.371 25.244,105.371 26.024,106.151 U10.8@27.097,106.151 27.097,106.981 C49.1@27.524,107.408
NetC54_1: C54.1 R30.5 R30.6 U9.1 | length 5
  Top Layer w0.254: R30.6@24.741,53.333 R30.5@24.741,52.463 25.244,52.463 26.024,51.683 U9.1@27.097,51.683 27.097,50.853 C54.1@27.524,50.426
NetC55_1: C55.1 R31.5 R31.6 U10.1 | length 5
  Top Layer w0.254: R31.6@24.741,103.701 R31.5@24.741,102.831 25.244,102.831 26.024,102.051 U10.1@27.097,102.051 27.097,101.221 C55.1@27.524,100.794
NetC58_1: C58.1 L1.1 U12.5
NetC58_2: C58.2 U12.6 | length 1.3
  Top Layer w0.25: U12.6@74.25,113.65 74.25,114.025 74.675,114.45 C58.2@74.675,114.725
NetC62_2: C62.2 D3.A R32.1 R33.2 U11.1 | length 12.9
  Top Layer w0.254: D3.A@2.625,99.375 2.65,99.4 2.65,100.725 2.9,100.975 R33.2@4.825,100.975 ; R32.1@4.825,102.475 R33.2@4.825,100.975 ; C62.2@8.25,95.5 8.25,98.83 U11.1@8.32,98.9 8.108,99.112 7.288,99.112 5.425,100.975 R33.2@4.825,100.975
NetC64_1: C64.1 C67.1 L3.1 U13.3 | length 5.1
  Top Layer w0.8: U13.3@33.399,119.884 34.065,120.55 C64.1@36.5,120.55 L3.1@38.2,120.55
NetC72_2: C72.2 U12.7 | length 0.9
  Top Layer w0.25: U12.7@73.75,113.65 C72.2@73.75,114.6
NetC73_2: C73.2 P19.12 | length 8.7
  Top Layer w0.4: P19.12@183.096,110.22 183.194,110.318 183.194,114.551 183.407,114.763 C73.2@187.425,114.763
NetC74_2: C74.2 P19.6 | length 7.5
  Top Layer w0.4: P19.6@182.08,112.76 182.08,114.361 183.419,115.7 C74.2@187.425,115.7
NetC75_2: C75.2 P19.1 | length 7.5
  Top Layer w0.4: C75.2@166.6,115.7 170.581,115.7 171.92,114.361 P19.1@171.92,112.76
NetC76_2: C76.2 P19.7 | length 8.7
  Top Layer w0.4: C76.2@166.6,114.763 167.938,114.763 ; 167.939,114.763 170.593,114.763 170.799,114.557 170.799,110.325 P19.7@170.904,110.22
NetC80_2: C80.2 R81.2 U14.3 | length 2.9
  Top Layer w0.254: R81.2@48.65,110.5 49.125,110.5 49.35,110.275 U14.3@49.35,109.2 C80.2@50.375,109.2
NetD2_A: D2.A FL1.3 J6.2 J6.3 | length 14.1
  Top Layer w2: FL1.3@92.35,132.95 D2.A@96.5,132.95 ; D2.A@96.6,132.85 99.95,132.85 100.3,132.5 ; J6.3@100.3,128 100.3,132.5 ; J6.2@100.3,134.1 100.3,132.5
NetD2_K: D2.K F6.2 FL1.1 | length 8.6
  Top Layer w1.1: FL1.1@92.35,128.65 92.71,128.29 F6.2@92.71,124.4
  Top Layer w2: FL1.1@92.35,128.65 92.415,128.715 D2.K@96.5,128.715
NetF6_1: F6.1 J6.1 | length 21.8
  Top Layer w1.1: F6.1@97.49,124.4 105.8,124.4 109.4,128 J6.1@111.7,128
  Top Layer w2: J6.1@111.7,128 J6.1@111.7,134.1
NetL4_2: L4.2 U13.2 | length 2.9
  Top Layer w1.1: U13.2@33.399,117.344 36.244,117.344 L4.2@36.3,117.4
NetLED1_A: LED1.A R2.1 | length 1.5
  Top Layer w0.254: R2.1@103.75,120 LED1.A@105.25,120
NetP19_14: P19.14 R83.1 | length 7.8
  Top Layer w0.2: R83.1@166.575,107.68 168.408,107.68 169.517,106.57 171.145,106.57 171.15,106.575 172.339,106.575 P19.14@173.444,107.68
NetP19_16: P19.16 R82.1 | length 4.5
  Top Layer w0.2: P19.16@183.096,107.68 R82.1@187.525,107.68
  Top Layer w0.254: P19.16@183.096,107.68 P19.16@183.121,107.655
NetP20_2: P20.2 R36.2 | length 2.2
  Top Layer w0.254: R36.2@160.08,119.475 160.08,118.445 160.125,118.4 160.125,118.393 160.6,117.918 P20.2@160.6,117.5
NetP21_2: P21.2 R84.2 | length 2.2
  Top Layer w0.152: R84.2@120.5,126 P21.2@122.73,126
NetR6_2: R6.2 U2.5 | length 21.1
  Top Layer w0.152: R6.2@43.112,114.432 43.112,113.788 43.6,113.3 49.9,113.3 54.472,117.872 U2.5@54.472,124.834
NetR10_2: R10.2 U2.4 | length 13.8
  Top Layer w0.152: R10.2@48.946,114.432 49.632,114.432 52.4,117.2 52.4,124.6 53.334,125.534 U2.4@53.772,125.534
NetR11_1: R11.1 R15.8 U2.13 | length 156.7
  Top Layer w0.152: R11.1@55.972,130 U2.13@55.972,127.734 57.088,127.734 57.254,127.9 v2(57.35,127.9) ; v1(133.83,24.35) R15.8@133.83,24.92
  Bottom Layer w0.152: v2(57.35,127.9) 58.094,127.9 59.289,126.705 59.289,95.811 88.044,67.056 88.044,44.801 100.913,31.932 129.589,31.932 133.798,27.723 133.798,24.382 v1(133.83,24.35)
NetR13_7: R13.7 U2.7 | length 150
  Top Layer w0.152: v2(55.3,123.025) 55.3,123.793 55.472,123.965 U2.7@55.472,124.834 ; v1(130.78,23.9) R13.7@130.78,24.92
  Bottom Layer w0.152: v2(55.3,123.025) 55.3,96.926 86,66.226 86,44 100.1,29.9 128.614,29.9 130.78,27.734 v1(130.78,23.9)
NetR13_8: R13.8 U2.6 | length 149.4
  Top Layer w0.152: U2.6@54.972,124.834 54.974,124.833 54.974,124.151 v2(54.975,124.15) ; v1(131.33,24.35) R13.8@131.33,24.92
  Bottom Layer w0.152: v2(54.975,124.15) 55.85,123.275 55.85,96.951 86.406,66.395 86.406,44.163 100.263,30.306 128.783,30.306 131.33,27.759 v1(131.33,24.35)
NetR15_5: R15.5 U2.10 | length 151.6
  Top Layer w0.152: U2.10@56.672,126.034 57.284,126.034 v2(57.325,126.075) ; v1(132.23,23.9) R15.5@132.23,24.92
  Bottom Layer w0.152: v2(57.325,126.075) 57.325,96.051 86.825,66.551 86.825,44.313 100.425,30.713 128.951,30.713 131.736,27.928 131.736,27.27 132.23,26.776 v1(132.23,23.9)
NetR15_6: R15.6 U2.11 | length 151.9
  Top Layer w0.152: U2.11@56.672,126.534 56.691,126.553 57.12,126.553 57.143,126.575 v2(57.925,126.575) ; v1(132.78,24.35) R15.6@132.78,24.92
  Bottom Layer w0.152: v2(57.925,126.575) 57.925,125.607 57.917,125.6 57.917,124.2 57.925,124.193 57.925,96.026 87.231,66.719 87.231,44.476 100.588,31.119 129.252,31.119 132.78,27.591 v1(132.78,24.35)
NetR15_7: R15.7 U2.12 | length 153.8
  Top Layer w0.152: U2.12@56.672,127.034 56.924,127.034 57.047,127.157 57.282,127.157 v2(57.35,127.225) ; v1(133.28,23.9) R15.7@133.28,24.92
  Bottom Layer w0.152: v2(57.35,127.225) 58.2,127.225 58.883,126.542 58.883,95.643 87.638,66.888 87.638,44.639 100.751,31.526 129.421,31.526 133.28,27.666 v1(133.28,23.9)
NetR17_2: R17.2 U2.1 | length 12.7
  Top Layer w0.152: R17.2@48.416,136.633 49.367,136.633 52.4,133.6 52.4,127.9 53.266,127.034 U2.1@53.772,127.034
NetR21_2: R21.2 U2.16 | length 19.8
  Top Layer w0.152: R21.2@42.582,136.633 42.582,137.243 43.072,137.733 49.467,137.733 54.472,132.728 U2.16@54.472,127.734
NetR33_1: R33.1 R34.2 | length 1.5
  Top Layer w0.254: R34.2@4.825,98.475 R33.1@4.825,99.975
NetR80_1: R80.1 U14.1 U14.4 | length 5.4
  Top Layer w0.254: U14.4@46.95,109.2 46.95,108.65 48.3,107.3 U14.1@49.35,107.3 49.35,106.225 49.1,105.975 R80.1@48.65,105.975
nFLT_IN: P13.1 R44.2 | length 5.2
  Top Layer w0.152: R44.2@123.909,130.821 123.909,134.139 P13.1@125.27,135.5
nFLT_OUT: P12.2 R43.2 | length 2.6
  Top Layer w0.152: R43.2@121.551,130.821 121.551,131.781 P12.2@122.73,132.96
PHY_LED0: JX1.167 P19.13 | length 35.8
  Top Layer w0.254: JX1.167@139.28,110.6 139.28,112.655 v2(139.3,112.675)
  Bottom Layer w0.152: v2(139.3,112.675) 161.025,112.675 166.045,107.655 170.879,107.655 P19.13@170.904,107.68
PHY_LED1: JX1.168 P19.15 | length 51.8
  Top Layer w0.152: JX1.168@139.78,110.6 139.8,110.62 v2(139.8,113.5)
  Bottom Layer w0.152: v2(139.8,113.5) 140.37,114.07 167.245,114.07 167.815,114.64 179.569,114.64 181.089,113.12 181.089,112.35 182.055,111.384 182.055,109.179 P19.15@180.556,107.68
PHY_MDI0_N: JX1.19 P19.10 U19.3 | length 58.8
  Top Layer w0.15: JX1.19@136.78,104.41 136.703,104.332 136.703,103.681 136.695,103.673 136.695,102.817 136.832,102.681 v2@136.832,102.6 ; v1(166.5,97.7) U19.3@167.05,97.7
  Bottom Layer w0.15: v2@136.832,102.6 136.832,102.519 136.695,102.383 136.695,102.096 142.095,96.696 166.074,96.696 166.193,96.816 166.193,97.393 v1(166.5,97.7) 166.823,97.377 166.823,96.784 166.911,96.696 171.371,96.696 179.141,104.466 179.141,108.266 179.883,109.008 179.883,109.369 P19.10@179.032,110.22
  other v2: 136.882,102.6
PHY_MDI0_P: JX1.20 P19.11 U19.4 | length 60.1
  Top Layer w0.15: v2@136.229,102.6 136.229,102.681 136.365,102.817 136.365,103.673 136.358,103.681 136.358,104.332 JX1.20@136.28,104.41 ; v1(166.5,95.3) U19.4@167.05,95.3
  Bottom Layer w0.15: v2@136.229,102.6 136.229,102.519 136.365,102.383 136.365,101.96 141.959,96.366 166.056,96.366 166.175,96.247 166.175,95.625 v1(166.5,95.3) 166.823,95.623 166.823,96.279 166.911,96.366 171.508,96.366 179.471,104.33 179.471,108.129 180.213,108.871 180.213,109.369 P19.11@181.064,110.22
  other v2: 136.179,102.6
PHY_MDI1_N: JX1.16 P19.5 U19.1 | length 62.6
  Top Layer w0.15: JX1.16@138.28,104.41 138.203,104.332 138.203,103.681 138.195,103.673 138.195,100.605 142.104,96.696 167.179,96.696 168.595,96.696 168.683,96.784 168.683,97.287 168.771,97.375 168.775,97.375 168.875,97.475 168.875,97.625 U19.1@168.95,97.7 ; U19.1@168.921,97.579 169.125,97.375 169.133,97.375 169.223,97.285 169.223,96.784 169.311,96.696 171.371,96.696 177.027,102.352 177.027,113.17 177.606,113.749 179.059,113.749 P19.5@180.048,112.76
PHY_MDI1_P: JX1.17 P19.4 U19.6 | length 60.5
  Top Layer w0.15: JX1.17@137.78,104.41 137.858,104.332 137.858,103.681 137.865,103.673 137.865,100.468 141.967,96.366 167.042,96.366 ; 167.042,96.366 168.603,96.366 168.691,96.279 168.691,95.709 U19.6@168.95,95.45 ; U19.6@168.95,95.3 U19.6@168.95,95.45 ; P19.4@178.016,112.76 177.926,112.85 177.38,112.85 177.357,112.827 177.357,102.215 171.508,96.366 169.311,96.366 169.223,96.279 169.223,95.713 169.135,95.625 169.125,95.625 U19.6@168.95,95.45
PHY_MDI2_N: JX1.13 P19.2 U18.3 | length 51.1
  Top Layer w0.15: JX1.13@139.78,104.41 139.703,104.332 139.703,103.681 139.695,103.673 139.695,102.792 139.832,102.656 v2@139.832,102.575 ; v1(166.5,102.2) U18.3@167.05,102.2
  Bottom Layer w0.15: v2@139.832,102.575 139.832,102.494 139.695,102.358 139.695,102.071 140.602,101.165 166.105,101.165 166.193,101.253 166.193,101.893 v1(166.5,102.2) 166.823,101.877 166.823,101.253 166.911,101.165 171.4,101.165 175.957,105.723 175.957,110.668 174.803,111.822 174.803,112.083 174.126,112.76 P19.2@173.952,112.76
  other v2: 139.882,102.575
PHY_MDI2_P: JX1.14 P19.3 U18.4 | length 52.2
  Top Layer w0.15: v2@139.229,102.575 139.229,102.656 139.365,102.792 139.365,103.673 139.358,103.681 139.358,104.332 JX1.14@139.28,104.41 ; v1(166.5,99.8) U18.4@167.05,99.8
  Bottom Layer w0.15: v2@139.229,102.575 139.229,102.494 139.365,102.358 139.365,101.935 140.465,100.835 166.087,100.835 166.175,100.747 166.175,100.125 v1(166.5,99.8) 166.823,100.123 166.823,100.747 166.911,100.835 171.536,100.835 172.021,101.319 176.287,105.586 176.287,110.805 175.133,111.959 175.133,112.083 175.81,112.76 P19.3@175.984,112.76
  other v2: 139.179,102.575
PHY_MDI3_N: JX1.10 P19.9 U18.1 | length 48.4
  Top Layer w0.15: JX1.10@141.28,104.41 141.203,104.332 141.203,103.681 141.195,103.673 141.195,103.461 143.491,101.165 168.595,101.165 168.683,101.253 168.683,101.787 168.771,101.875 168.775,101.875 168.875,101.975 168.875,102.125 U18.1@168.95,102.2 ; U18.1@168.921,102.079 169.125,101.875 169.133,101.875 169.223,101.785 169.223,101.253 169.311,101.165 170.351,101.165 171.4,101.165 175.955,105.72 175.955,110.629 175.377,111.207 174.556,111.207 174.117,110.768 174.117,110.644 174.205,110.556 174.26,110.556 174.596,110.22 P19.9@174.968,110.22
PHY_MDI3_P: JX1.11 P19.8 U18.6 | length 50.7
  Top Layer w0.15: JX1.11@140.78,104.41 140.858,104.332 140.858,103.681 140.865,103.673 140.865,103.324 143.355,100.835 168.603,100.835 168.691,100.747 168.691,100.209 U18.6@168.95,99.95 ; P19.8@172.936,110.22 173.308,110.22 173.644,110.556 173.699,110.556 173.787,110.644 173.787,110.905 174.419,111.537 175.514,111.537 176.285,110.766 176.285,105.584 171.536,100.835 170.215,100.835 169.311,100.835 169.223,100.747 169.223,100.213 169.135,100.125 169.125,100.125 U18.6@168.95,99.95 ; U18.6@168.95,99.95 U18.6@168.95,99.8 U18.6@168.95,99.95
PWM0: JX2.78 R62.5 | length 2.5
  Top Layer w0.152: JX2.78@139.78,34.6 139.78,36.588 R62.5@139.78,37.096
PWM1: JX2.79 R62.6 | length 2.5
  Top Layer w0.152: JX2.79@140.28,34.6 140.28,36.588 R62.6@140.28,37.096
PWM2: JX2.80 R62.7 | length 2.5
  Top Layer w0.152: JX2.80@140.78,34.6 140.78,36.588 R62.7@140.78,37.096
PWM3: JX2.81 R62.8 | length 2.5
  Top Layer w0.152: JX2.81@141.28,34.6 141.28,36.588 R62.8@141.28,37.096
PWM4: JX2.83 R64.5 | length 2.5
  Top Layer w0.152: JX2.83@142.28,34.6 142.28,36.588 R64.5@142.28,37.096
PWM5: JX2.84 R64.6 | length 2.5
  Top Layer w0.152: JX2.84@142.78,34.6 142.78,36.588 R64.6@142.78,37.096
PWM6: JX2.85 R64.7 | length 2.5
  Top Layer w0.152: JX2.85@143.28,34.6 143.28,36.588 R64.7@143.28,37.096
PWM7: JX2.86 R64.8 | length 2.5
  Top Layer w0.152: JX2.86@143.78,34.6 143.78,36.588 R64.8@143.78,37.096
PWM8: JX2.103 R63.8 | length 2.5
  Top Layer w0.152: R63.8@139.78,25.92 JX2.103@139.78,28.41
PWM9: JX2.102 R63.7 | length 2.5
  Top Layer w0.152: R63.7@140.28,25.92 JX2.102@140.28,28.41
PWM10: JX2.101 R63.6 | length 2.5
  Top Layer w0.152: R63.6@140.78,25.92 JX2.101@140.78,28.41
PWM11: JX2.100 R63.5 | length 2.5
  Top Layer w0.152: R63.5@141.28,25.92 JX2.100@141.28,28.41
PWM12: JX2.98 R65.8 | length 2.5
  Top Layer w0.152: R65.8@142.28,25.92 JX2.98@142.28,28.41
PWM13: JX2.97 R65.7 | length 2.5
  Top Layer w0.152: R65.7@142.78,25.92 JX2.97@142.78,28.41
PWM14: JX2.96 R65.6 | length 2.5
  Top Layer w0.152: R65.6@143.28,25.92 JX2.96@143.28,28.41
PWM15: JX2.95 R65.5 | length 2.5
  Top Layer w0.152: R65.5@143.78,25.92 JX2.95@143.78,28.41
PWM-0: P8.2 R62.4 R67.4 TP100.1 | length 90.7
  Top Layer w0.152: R62.4@139.73,38.096 139.73,41.36 142.052,43.682 v1(171.019,43.682) ; R67.4@169.575,77.504 169.575,76.925 170.033,76.467 170.967,76.467 v1(171,76.5) TP100.1@177.5,76.5
  Top Layer w0.25: TP100.1@177.5,76.5 P8.2@191.2,76.5
  Bottom Layer w0.152: v1(171,76.5) 171.019,76.481 v1(171.019,43.682)
PWM-1: P8.3 R62.3 R67.3 TP92.1 | length 89.5
  Top Layer w0.152: R62.3@140.28,38.096 140.28,40.767 142.397,42.884 v1(170.003,42.884) ; R67.3@169.025,77.504 169.025,73.975 v1(170,73) TP92.1@177.5,73
  Top Layer w0.25: TP92.1@177.5,73 P8.3@191.2,73
  Bottom Layer w0.152: v1(170,73) 170.001,72.999 170.001,42.885 v1(170.003,42.884)
PWM-2: P8.4 R62.2 R67.2 TP84.1 | length 88.9
  Top Layer w0.152: R62.2@140.78,38.096 140.78,40.175 142.691,42.085 v1(168.987,42.085) ; R67.2@168.525,77.504 168.525,69.975 v1(169,69.5) TP84.1@177.5,69.5
  Top Layer w0.25: TP84.1@177.5,69.5 P8.4@191.2,69.5
  Bottom Layer w0.152: v1(168.987,42.085) 168.993,42.092 168.993,69.493 v1(169,69.5)
PWM-3: P8.5 R62.1 R67.1 TP72.1 | length 88.3
  Top Layer w0.152: R62.1@141.33,38.096 141.33,39.582 143.035,41.287 v1(167.971,41.287) ; R67.1@167.975,77.504 167.987,77.491 167.987,66.013 v1(168,66) TP72.1@177.5,66
  Top Layer w0.25: TP72.1@177.5,66 P8.5@191.2,66
  Bottom Layer w0.152: v1(167.971,41.287) 167.985,41.302 167.985,65.985 v1(168,66)
PWM-4: P6.2 R64.4 R66.4 TP99.1 | length 71.9
  Top Layer w0.152: R64.4@142.23,38.096 142.23,39.415 143.304,40.489 v1(166.955,40.489) ; R66.4@165.511,60.549 165.511,59.689 166.226,58.974 166.974,58.974 v1(167,59) TP99.1@177.5,59
  Top Layer w0.25: TP99.1@177.5,59 P6.2@191.2,59
  Bottom Layer w0.152: v1(166.955,40.489) 166.977,40.511 166.977,58.977 v1(167,59)
PWM-5: P6.3 R64.3 R66.3 TP91.1 | length 70.9
  Top Layer w0.152: R64.3@142.78,38.096 142.78,38.924 143.543,39.687 165.935,39.687 v1(165.943,39.694) ; R66.3@164.961,60.549 164.961,56.439 v1(165.9,55.5) TP91.1@177.5,55.5
  Top Layer w0.25: TP91.1@177.5,55.5 P6.3@191.2,55.5
  Bottom Layer w0.152: v1(165.9,55.5) 165.921,55.479 165.921,39.715 v1(165.943,39.694)
PWM-6: P6.4 R64.2 R66.2 TP83.1 | length 70.3
  Top Layer w0.152: R64.2@143.28,38.096 143.28,38.484 143.692,38.896 v1@164.85,38.896 ; R66.2@164.461,60.549 164.461,52.439 v1(164.9,52) TP83.1@177.5,52
  Top Layer w0.25: TP83.1@177.5,52 P6.4@191.2,52
  Bottom Layer w0.152: v1(164.9,52) 164.913,51.987 164.913,38.909 v1(164.927,38.896)
PWM-7: P6.5 R64.1 R66.1 TP71.1 | length 69.7
  Top Layer w0.152: R64.1@143.83,38.096 v1@163.911,38.096 ; R66.1@163.911,60.384 163.905,60.379 163.905,48.505 v1(163.9,48.5) TP71.1@177.5,48.5
  Top Layer w0.25: TP71.1@177.5,48.5 P6.5@191.2,48.5
  Bottom Layer w0.152: v1(163.9,48.5) 163.905,48.495 163.905,38.103 v1(163.911,38.098)
PWM-8: P4.2 R63.1 R69.4 TP98.1 | length 91.9
  Top Layer w0.152: R63.1@139.73,24.92 139.73,21.293 142.498,18.525 155.664,18.525 155.739,18.6 v1(169,18.6) ; R69.4@168.927,28.601 168.964,28.637 168.964,41.364 169.05,41.45 177.45,41.45 TP98.1@177.5,41.5
  Top Layer w0.25: TP98.1@177.5,41.5 P4.2@191.2,41.5
  Bottom Layer w0.152: v1(169,18.6) v1(169,41.4)
PWM-9: P4.3 R63.2 R69.3 TP90.1 | length 83.2
  Top Layer w0.152: R63.2@140.28,24.92 140.28,22.013 142.97,19.323 156.399,19.323 156.475,19.4 v1(170,19.4) ; R69.3@169.477,28.601 169.477,37.477 v1(170,38) TP90.1@177.5,38
  Top Layer w0.25: TP90.1@177.5,38 P4.3@191.2,38
  Bottom Layer w0.152: v1(170,19.4) v1(170,38)
PWM-10: P4.4 R63.3 R69.2 TP82.1 | length 74.4
  Top Layer w0.152: R63.3@140.78,24.92 140.78,22.783 143.463,20.1 v1(171,20.1) ; R69.2@169.977,28.601 169.977,33.477 v1(171,34.5) TP82.1@177.5,34.5
  Top Layer w0.25: TP82.1@177.5,34.5 P4.4@191.2,34.5
  Bottom Layer w0.152: v1(171,20.1) 171,27.382 170.981,27.401 170.981,27.801 171,27.819 v1(171,34.5)
PWM-11: P4.5 R63.4 R69.1 TP70.1 | length 66.1
  Top Layer w0.152: R63.4@141.33,24.92 141.33,23.503 143.933,20.9 v1(172,20.9) ; R69.1@170.527,28.601 170.527,30.222 171.406,31.1 v1(172,31.1) 172.05,31.05 177.45,31.05 TP70.1@177.5,31
  Top Layer w0.25: TP70.1@177.5,31 P4.5@191.2,31
  Bottom Layer w0.152: v1(172,20.9) v1(172,31.1)
PWM-12: P2.2 R65.1 R68.4 TP97.1 | length 61.7
  Top Layer w0.152: R65.1@142.23,24.92 142.23,23.51 144.022,21.718 v1(172.778,21.718) 172.978,21.718 175.218,21.718 TP97.1@177.5,24 ; R68.4@172.778,12.073 v1(172.778,13.064)
  Top Layer w0.25: TP97.1@177.5,24 P2.2@191.2,24
  Bottom Layer w0.152: v1(172.778,13.064) v1(172.778,21.718)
